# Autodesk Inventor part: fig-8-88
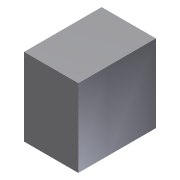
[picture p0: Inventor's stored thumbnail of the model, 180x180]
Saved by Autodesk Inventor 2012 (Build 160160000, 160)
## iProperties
Created: 2009-04
Part Number: fig-8-88
Document SubType Name: Modeling
Designer: Sham
Density: 1 g/cm^3
Material: Default
Author: Sham
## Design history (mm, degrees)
sketch "Sketch5"
  geometry: L1 (14, -20)-(0, -20); L2 (0, -20)-(0, 0); L3 (0, 0)-(14, 0); L4 (14, 0)-(14, -20)
  constraints: 8 end point
extrude "Extrusion2" new body sketch "Sketch5" distance "d3" = 20; taper "d4" = 0 deg
sketch "Sketch6"
  geometry: L1 (-5, 12)-(17, 7)
  constraints: 2 end point
split "Split8" sketch "Sketch6"
  body "Solid2"
body "Solid3"
body "Solid4"
